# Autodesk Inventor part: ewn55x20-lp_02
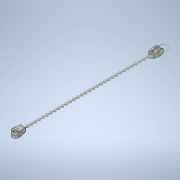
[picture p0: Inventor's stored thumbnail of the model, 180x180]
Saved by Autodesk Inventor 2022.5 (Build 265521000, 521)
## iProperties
Created: 2021-08
Part Number: ewn55x20-lp_02
Material: 一般
Document SubType Name: Modeling
Designer: ImaoCorp
Density: 1 g/cm^3
Appearance: 既定
Author: ImaoCorp
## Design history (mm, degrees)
feature "ewn55x20-lp_02"
node "ソリッド1"
